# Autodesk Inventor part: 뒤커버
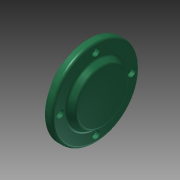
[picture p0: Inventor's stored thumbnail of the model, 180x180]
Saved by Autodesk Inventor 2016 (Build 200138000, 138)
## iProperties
Created: 2015-11
Part Number: 뒤커버
Material: 알루미늄 6061
Document SubType Name: Modeling
Designer: mduedu
Density: 2.71 g/cm^3
Appearance: 매끄러움 - 짙은 바다 녹색
Mass: 264.356 g
Surface Area: 212.727 cm^2
Volume: 97.5485 cm^3
Author: mduedu
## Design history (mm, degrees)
sketch "스케치1"
  geometry: C1 r 47.5 at (0, 0); 1 further point
  constraints: 1 centre point, 1 coincident
  dimensions: "d42" = 95 diameter of C1
extrude "돌출1" new body sketch "스케치1" distance "d3" = 8; taper "d4" = 0 deg
sketch "스케치2"
  geometry: C1 r 32.5 at (0, 0); 1 further point
  constraints: 1 centre point, 1 coincident
  dimensions: "d5" = 65 diameter of C1
extrude "돌출2" join sketch "스케치2" distance "d6" = 7; taper "d7" = -30 deg
sketch "스케치5" dims "d44" = 78
  geometry: 3 further points
  constraints: 2 vertical alignment, 1 coincident, 2 other
hole "구멍3" sketch "스케치5" at (0, 39) diameter "d45" = 4.5; stored, may be unused: countersink angle "d49" = 90 deg, drill point angle "d51" = 118 deg; dims "d46" = 6, "d47" = 8, "d48" = 4.4, "d50" = 8
sketch "스케치4"
  geometry: C1 r 32.5 at (0, 0); 1 further point
  constraints: 1 centre point, 1 coincident
  dimensions: "d21" = 65 diameter of C1
extrude "돌출3" join sketch "스케치4" distance "d23" = 12; taper "d24" = 0 deg
hole "구멍2" diameter "d27" = 34; stored, may be unused: countersink angle "d31" = 90 deg, drill point angle "d33" = 0 deg; dims "d28" = 6, "d29" = 40, "d30" = 12, "d32" = 15, "d62" = 10, "d63" = 10
fillet "모깎기3" dims "d36" = 3
fillet "모깎기4" dims "d37" = 3
fillet "모깎기5" dims "d38" = 0.3
chamfer "모따기1" distance "d39" = 1; stored, may be unused: second distance "d40" = 2, angle "d41" = 45 deg
node "솔리드1"
pattern_circular "원형 패턴2" dims angle "d53" = 360 deg
